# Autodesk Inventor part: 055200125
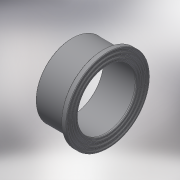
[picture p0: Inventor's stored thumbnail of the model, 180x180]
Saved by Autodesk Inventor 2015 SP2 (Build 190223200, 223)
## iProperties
Created: 2017-10
Part Number: 055200125
Material: Generic
Description: PLASSON FLANGE(FLAT GASKET)C 125
Document SubType Name: Modeling
Designer: KIM
Density: 1 g/cm^3
Appearance: Default
Author: KIM
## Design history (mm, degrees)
derived "055200.ipt"
feature "Solid1::055200.ipt"
tag "TaggingFeature1"
body "Solid1"
other parameters: "d0" = 74, "d1" = 146, "d2" = 125, "d3" = 118.75, "d4" = 11, "d5" = 69, "d6" = 169, "d8" = 3.3, "d11" = 1.25, "d12" = 1.65, "d_" = 125, "E_" = 146, "E_1" = 169, "l_" = 69, "B_" = 11, "H_" = 74, "d14" = 25.125
